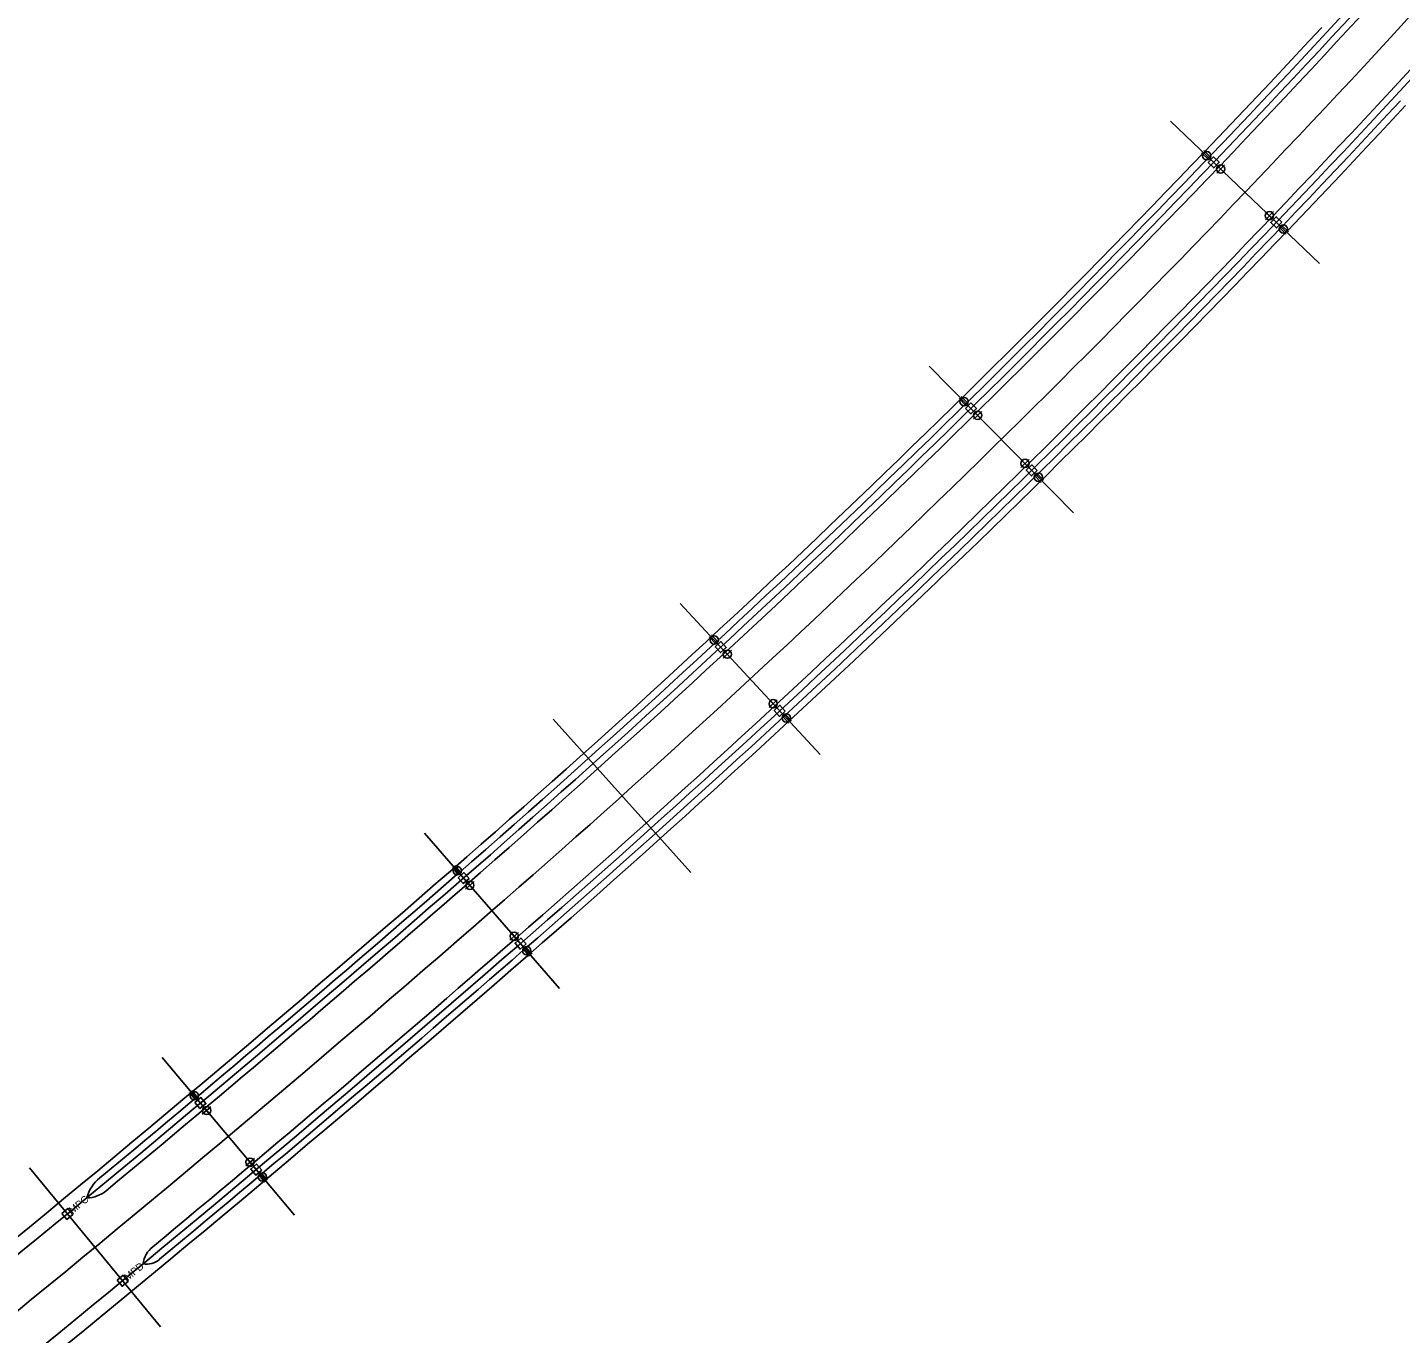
# Model space of a CAD drawing. Extents: x 927572 to 929124, y 636573 to 637910.
# Drawn here: x 928607.2 to 928805.1, y 636965.5 to 637153.6 of the extents above; entities that cross this region are included whole.
import ezdxf

# ---------------------------------------------------------------- set-up
doc = ezdxf.new("R2010")
doc.units = 0
for name, color, linetype in [('ConduitOT', 7, 'Continuous'), ('Miscellaneous4', 7, 'Continuous'), ('Miscellaneous7', 7, 'Continuous'), ('ScratchEle_dp', 7, 'Continuous')]:
    doc.layers.add(name, color=color, linetype=linetype)

msp = doc.modelspace()

# ---------------------------------------------------------------- linework, layer by layer
at = {"layer": 'ConduitOT'}
for centre, radius, start, end in [((927949.43, 637937.64), 1153.17, 317.11857, 343.93655), ((927949.43, 637937.64), 1155.17, 317.11857, 343.92577), ((927949.43, 637937.64), 1165.67, 317.11857, 343.95974), ((927949.43, 637937.64), 1154.17, 317.11857, 328.20354), ((927949.43, 637937.64), 1166.67, 317.11857, 328.20383), ((927591.11, 638270.4), 1641.17, 311.0304, 317.11857), ((927591.11, 638270.4), 1642.17, 311.0304, 317.11857), ((927591.11, 638270.4), 1643.17, 311.0304, 317.11857), ((927591.11, 638270.4), 1644.17, 311.0304, 317.11857), ((927591.11, 638270.4), 1654.67, 311.0304, 317.11857), ((927591.11, 638270.4), 1655.67, 311.0304, 317.11857), ((927591.11, 638270.4), 1656.67, 311.0304, 317.11857), ((927591.11, 638270.4), 1657.67, 311.0304, 317.11857), ((926819.39, 639157.21), 2816.74, 302.71158, 311.0304), ((926819.39, 639157.21), 2818.74, 302.71158, 311.0304), ((926819.39, 639157.21), 2817.74, 309.65674, 311.0304), ((926819.39, 639157.21), 2819.74, 309.64715, 311.0304), ((926819.39, 639157.21), 2831.24, 302.71158, 311.0304), ((926819.39, 639157.21), 2830.24, 309.64707, 311.0304), ((926819.39, 639157.21), 2832.24, 309.63891, 311.0304), ((926819.39, 639157.21), 2833.24, 302.71158, 311.0304), ((928620.72, 636983.79), 5.12, 127.0326, 166.158), ((928615.71, 636989.46), 4.45, 270.5328, 309.6471), ((928627.38, 636975.1), 3.55, 126.8215, 173.735), ((928624.28, 636978.48), 3.03, 261.7343, 309.6389)]:
    msp.add_arc(centre, radius, start, end, dxfattribs=at)
at = {"layer": 'Miscellaneous4'}
for p, q in [((928776.38, 637135.54), (928777.37, 637134.59)), ((928776.69, 637135.87), (928777.68, 637134.91)), ((928777.72, 637134.57), (928777.56, 637134.72)), ((928778.53, 637133.79), (928779.72, 637132.65)), ((928778.56, 637132.63), (928779.69, 637133.81)), ((928786.75, 637125.92), (928785.56, 637127.06)), ((928786.73, 637127.08), (928785.59, 637125.9)), ((928787.56, 637125.14), (928787.73, 637124.99)), ((928788.91, 637124.17), (928787.91, 637125.12)), ((928788.59, 637123.85), (928787.6, 637124.8)), ((928741.44, 637100.14), (928742.4, 637099.16)), ((928741.76, 637100.45), (928742.72, 637099.47)), ((928742.75, 637099.12), (928742.59, 637099.28)), ((928743.53, 637097.16), (928744.7, 637098.31)), ((928743.54, 637098.32), (928744.69, 637097.15)), ((928751.52, 637091.37), (928750.35, 637090.22)), ((928751.51, 637090.21), (928750.36, 637091.38)), ((928752.3, 637089.41), (928752.46, 637089.25)), ((928753.29, 637088.08), (928752.33, 637089.06)), ((928753.61, 637088.39), (928752.65, 637089.37)), ((928705.44, 637065.81), (928706.37, 637064.8)), ((928705.77, 637066.12), (928706.7, 637065.11)), ((928706.72, 637064.76), (928706.57, 637064.92)), ((928707.44, 637062.77), (928708.65, 637063.89)), ((928707.48, 637063.93), (928708.6, 637062.72)), ((928715.25, 637056.74), (928714.05, 637055.63)), ((928715.21, 637055.58), (928714.09, 637056.79)), ((928715.97, 637054.76), (928716.13, 637054.59)), ((928716.92, 637053.4), (928715.99, 637054.41)), ((928717.25, 637053.7), (928716.32, 637054.71)), ((928668.42, 637032.59), (928669.32, 637031.55)), ((928668.76, 637032.88), (928669.66, 637031.85)), ((928669.67, 637031.5), (928669.52, 637031.67)), ((928670.32, 637029.49), (928671.56, 637030.57)), ((928670.4, 637030.65), (928671.48, 637029.41)), ((928677.95, 637023.23), (928676.71, 637022.15)), ((928677.87, 637022.07), (928676.79, 637023.31)), ((928678.61, 637021.22), (928678.76, 637021.05)), ((928679.52, 637019.83), (928678.62, 637020.87)), ((928679.86, 637020.13), (928678.96, 637021.17)), ((928630.87, 637000.49), (928631.75, 636999.43)), ((928630.53, 637000.2), (928631.41, 636999.15)), ((928631.76, 636999.08), (928631.61, 636999.26)), ((928632.38, 636997.06), (928633.64, 636998.12)), ((928632.48, 636998.22), (928633.54, 636996.96)), ((928639.89, 636990.67), (928638.64, 636989.61)), ((928639.79, 636989.51), (928638.74, 636990.77)), ((928640.52, 636988.65), (928640.66, 636988.48)), ((928641.75, 636987.54), (928640.86, 636988.59)), ((928641.4, 636987.25), (928640.52, 636988.3))]:
    msp.add_line(p, q, dxfattribs=at)
for centre in [(928777.13, 637135.13), (928779.13, 637133.22), (928786.16, 637126.49), (928788.16, 637124.58), (928742.17, 637099.71), (928744.11, 637097.74), (928750.94, 637090.8), (928752.88, 637088.82), (928706.16, 637065.36), (928708.04, 637063.33), (928714.65, 637056.18), (928716.53, 637054.15), (928669.13, 637032.12), (928670.94, 637030.03), (928677.33, 637022.69), (928679.15, 637020.6), (928631.23, 636999.71), (928633.01, 636997.59), (928639.27, 636990.14), (928641.05, 636988.02)]:
    msp.add_circle(centre, 0.597, dxfattribs=at)
at = {"layer": 'Miscellaneous7'}
for points in [[(928777.33, 637134.16), (928778.11, 637134.97), (928778.92, 637134.19), (928778.14, 637133.38)], [(928787.95, 637125.55), (928787.17, 637124.74), (928786.36, 637125.52), (928787.14, 637126.33)], [(928742.35, 637098.73), (928743.15, 637099.52), (928743.94, 637098.72), (928743.14, 637097.93)], [(928752.7, 637089.8), (928751.9, 637089.01), (928751.11, 637089.82), (928751.91, 637090.6)], [(928706.31, 637064.37), (928707.13, 637065.14), (928707.9, 637064.31), (928707.07, 637063.55)], [(928716.39, 637055.14), (928715.56, 637054.37), (928714.8, 637055.2), (928715.62, 637055.96)], [(928669.24, 637031.13), (928670.09, 637031.87), (928670.83, 637031.02), (928669.98, 637030.28)], [(928679.04, 637021.59), (928678.19, 637020.85), (928677.45, 637021.7), (928678.3, 637022.44)], [(928631.32, 636998.72), (928632.19, 636999.45), (928632.91, 636998.58), (928632.05, 636997.86)], [(928640.95, 636989.01), (928640.09, 636988.29), (928639.36, 636989.15), (928640.22, 636989.87)], [(928612.15, 636982.77), (928613.02, 636983.49), (928613.74, 636982.62), (928612.87, 636981.9)], [(928620.11, 636973.14), (928620.98, 636973.85), (928621.7, 636972.98), (928620.83, 636972.27)]]:
    msp.add_lwpolyline(points, close=True, dxfattribs=at)
at = {"layer": 'ScratchEle_dp'}
for p, q in [((928793.36, 637119.6), (928771.93, 637140.11)), ((928757.93, 637083.69), (928737.13, 637104.84)), ((928721.42, 637048.87), (928701.27, 637070.64)), ((928702.78, 637031.88), (928682.96, 637053.96)), ((928702.78, 637031.88), (928682.96, 637053.96)), ((928683.88, 637015.17), (928664.4, 637037.55)), ((928645.68, 636982.51), (928626.6, 637005.23)), ((928626.36, 636966.43), (928607.48, 636989.32))]:
    msp.add_line(p, q, dxfattribs=at)
for centre, radius, start, end in [((927949.43, 637937.64), 1160.42, 317.11857, 357.69675), ((927591.11, 638270.4), 1649.42, 311.0304, 317.11857), ((926819.39, 639157.21), 2824.99, 302.71158, 311.0304)]:
    msp.add_arc(centre, radius, start, end, dxfattribs=at)

# ---------------------------------------------------------------- texts
at = {"layer": 'Miscellaneous4'}
for s, p in [('MPC', (928613.71, 636982.65)), ('MPD', (928621.67, 636973.01))]:
    msp.add_text(s, height=1.05, rotation=39.5315, dxfattribs=at).set_placement(p)

doc.saveas('drawing.dxf')
